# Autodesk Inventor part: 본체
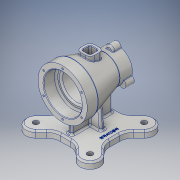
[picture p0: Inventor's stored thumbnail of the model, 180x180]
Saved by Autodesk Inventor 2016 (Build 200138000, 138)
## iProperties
Created: 2018-03
Part Number: 본체
Material: 알루미늄 6061
Document SubType Name: Modeling
Designer: USER
Density: 2.7 g/cm^3
Appearance: 알루미늄 - 평지
Mass: 1010.51 g
Surface Area: 856.88 cm^2
Volume: 374.263 cm^3
Author: USER
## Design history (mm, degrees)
sketch "스케치1"
  geometry: L1 (0, 50)-(0, -50); L2 (36, 50)-(45, 50); L3 (45, 50)-(45, 30.45); L4 (44.868, 29.57)-(27.632, -26.57); L5 (27.5, -27.45)-(27.5, -50); L6 (27.5, -50)-(21, -50); L7 (35, 49)-(35, 30); L8 (32, 27)-(29, 27); L9 (26, 24)-(26, -17); L10 (23, -20)-(23, -20); L11 (20, -23)-(20, -49); L12 (36, 50)-(35, 49); L13 (20, -49)-(21, -50); A1 r 3 centre (32, 30) between (32, 27) and (35, 30); A2 r 3 centre (29, 24) between (29, 27) and (26, 24); A3 r 3 centre (23, -17) between (23, -20) and (26, -17); A4 r 3 centre (42, 30.45) between (44.868, 29.57) and (45, 30.45); A5 r 3 centre (30.5, -27.45) between (27.632, -26.57) and (27.5, -27.45); A6 r 3 centre (23, -23) between (23, -20) and (20, -23); 9 further points
  constraints: 26 end point, 14 point on line, 12 point on circle, 12 tangent, 6 centre point, 5 perpendicular, 4 equal radius, 2 horizontal alignment, 2 vertical, 1 coincident, 1 horizontal, 1 midpoint, 1 parallel
  dimensions: "d0" = 100 distance of L1.start L1.end; "d1" = 70 diameter of L7 L1; "d2" = 52 diameter of L9 L1; "d3" = 40 diameter of L11 L1; "d4" = 90 diameter of L3 L1; "d5" = 55 diameter of L5 L1; "d6" = 77 distance from line of point (27.5, -27) L2; "d7" = 20 distance of L2.end point (45, 30); "d8" = 23 distance of point (35, 50) point (35, 27); "d9" = 47 distance of point (26, 27) point (26, -20); "d10" = 3 radius of A1; "d11" = 1 distance of L2.start point (35, 50); "d12" = 1 distance of L7.start point (35, 50) (= d11); "d13" = 1 distance of L11.end point (20, -50) (= d11); "d14" = 1 distance of L6.end point (20, -50) (= d13); "d15" = 3 radius of A6
revolve "회전1" sketch "스케치1" stored, may be unused: angle "d16" = 90 deg
sketch "스케치2"
  geometry: A1 r 27.5 centre (0, 0) between (0, 27.5) and (-6.943, 26.609) reference; A2 r 7 centre (0, 27.5) between (6.943, 26.609) and (-6.943, 26.609); 1 further point
  constraints: 5 point on circle, 1 centre point, 1 vertical alignment
  dimensions: "d17" = 7 radius of A2
extrude "돌출1" join sketch "스케치2" distance "d18" = 15; taper "d19" = 0 deg
sketch "스케치3"
  geometry: A1 r 7 centre (0, 0) between (6.943, -0.891) and (-6.943, -0.891) reference; 2 further points
  constraints: 1 coincident
hole "구멍1" sketch "스케치3" at (0, 0) diameter "d20" = 3.242; stored, may be unused: countersink angle "d24" = 90 deg, drill point angle "d26" = 118 deg; dims "d21" = 9, "d22" = 4, "d23" = 2, "d25" = 11
fillet "모깎기1" dims "d30" = 1
node "작업 평면1"
sketch "스케치4"
  geometry: L1 (-45, 45)-(45, 45); L2 (45, 45)-(45, -45); L3 (45, -45)-(-45, -45); L4 (-45, -45)-(-45, 45); L5 (-45, 45)-(45, -45); L6 (52.616, 52.616)-(-45, -45); 2 further points
  constraints: 12 end point, 2 parallel, 2 perpendicular, 2 point on line, 1 coincident, 1 horizontal, 1 midpoint, 3 other
  dimensions: "d32" = 90 distance of L1.end L2.end
extrude "돌출2" join sketch "스케치4" distance "d33" = 12; taper "d34" = 0 deg
sketch "스케치6"
  geometry: L1 (45, -45)-(45, 45) reference; L2 (-45, 45)-(45, 45) reference; L3 (-49.497, -49.497)-(49.497, 49.497); L4 (36.77, 62.225)-(19.544, 45); L5 (62.225, 36.77)-(45, 19.544); L6 (45, -45)-(-45, -45) reference; L7 (-45, -45)-(-45, 45) reference; L8 (-49.497, 49.497)-(49.497, -49.497); L9 (62.225, -36.77)-(45, -19.544); L10 (-36.77, -62.225)-(-19.544, -45); L11 (-62.225, 36.77)-(-45, 19.544); L12 (-36.77, 62.225)-(-19.544, 45); L13 (36.77, -62.225)-(19.544, -45); L14 (-62.225, -36.77)-(-45, -19.544); C1 r 5 at (49.497, 49.497); C2 r 5 at (49.497, -49.497); C3 r 5 at (-49.497, -49.497); C4 r 5 at (-49.497, 49.497); A1 r 70 centre (0, 0) between (49.497, 49.497) and (-49.497, -49.497); A2 r 18 centre (49.497, 49.497) between (62.225, 36.77) and (36.77, 62.225); A3 r 18 centre (49.497, -49.497) between (36.77, -62.225) and (62.225, -36.77); A4 r 18 centre (-49.497, -49.497) between (-62.225, -36.77) and (-36.77, -62.225); A5 r 18 centre (-49.497, 49.497) between (-36.77, 62.225) and (-62.225, 36.77); 1 further point
  constraints: 20 end point, 12 point on circle, 9 centre point, 9 coincident, 8 parallel, 8 point on line, 8 tangent, 6 equal radius, 2 midpoint
  dimensions: "d35" = 140 diameter of A1; "d36" = 45 deg angle of L3 L2; "d37" = 10 diameter of C1; "d38" = 18 radius of A2; "d39" = 45 deg angle of L8 L6
extrude "돌출3" join sketch "스케치6" distance "d40" = 12; taper "d41" = 0 deg
fillet "모깎기2" dims "d42" = 25
chamfer "모따기1" distance "d43" = 3; stored, may be unused: second distance "d44" = 2, angle "d45" = 45 deg
sketch "스케치7"
  geometry: L1 (4, -37)-(-4, -37); L2 (-4, -37)-(-4, 37); L3 (-4, 37)-(4, 37); L4 (4, 37)-(4, -37); L5 (4, -37)-(-4, 37); L6 (-4, -37)-(4, 37); 2 further points
  constraints: 12 end point, 4 midpoint, 2 parallel, 1 horizontal, 1 perpendicular
  dimensions: "d46" = 8 distance between parallel lines of L4 L2; "d47" = 37 vertical distance of L1.end point (0, 0)
extrude "돌출4" join sketch "스케치7" stored distance "d48" = 12; taper "d49" = 0 deg
sketch "스케치8"
  geometry: L1 (-4, -70)-(4, -70) reference; L2 (4, -70)-(-4, -70) reference; L3 (44.497, -70)-(54.497, -70) reference; L4 (-54.497, -70)-(-44.497, -70) reference; L5 (-54.497, -70)-(-44.497, -70) reference; L6 (44.497, -70)-(54.497, -70) reference; L7 (50.201, -70)-(42, -70) reference; L8 (60.104, -70)-(50.201, -70) reference; L9 (38.891, -70)-(60.104, -70) reference; L10 (28.988, -70)-(38.891, -70) reference; L11 (9.189, -70)-(28.988, -70) reference; L12 (-9.189, -70)-(9.189, -70) reference; L13 (-28.988, -70)-(-9.189, -70) reference; L14 (-38.891, -70)-(-28.988, -70) reference; L15 (-60.104, -70)-(-38.891, -70) reference; L16 (-50.201, -70)-(-60.104, -70) reference; L17 (-42, -70)-(-50.201, -70) reference; L18 (-50.201, -70)-(-42, -70) reference; L19 (-60.104, -70)-(-50.201, -70) reference; L20 (-38.891, -70)-(-60.104, -70) reference; L21 (-28.988, -70)-(-38.891, -70) reference; L22 (-9.189, -70)-(-28.988, -70) reference; L23 (9.189, -70)-(-9.189, -70) reference; L24 (28.988, -70)-(9.189, -70) reference; L25 (38.891, -70)-(28.988, -70) reference; L26 (60.104, -70)-(38.891, -70) reference; L27 (50.201, -70)-(60.104, -70) reference; L28 (42, -70)-(50.201, -70) reference; L29 (-38.891, -70)-(-28.988, -70) reference; L30 (-24, -70)-(-21.979, -46.903); L31 (28.988, -70)-(38.891, -70) reference; L32 (24, -70)-(22.037, -47.558); 1 further point
  constraints: 4 end point, 2 point on line
  dimensions: "d50" = 24 horizontal distance of L30.start point (0, 0); "d51" = 24 horizontal distance of L32.start point (0, 0); "d52" = 95 deg angle of L30 L21; "d53" = 95 deg angle of L32 L25
  node "투영된 루프1"
feature "리브1" dims "d54" = 1, "d55" = 8, "d56" = 0, "d57" = 0, "d58" = 1, "d59" = 1
feature "리브2" dims "d60" = 1, "d61" = 8, "d62" = 0, "d63" = 0, "d64" = 1, "d65" = 1
fillet "모깎기3" dims "d66" = 3
fillet "모깎기4" dims "d67" = 3
sketch "스케치9"
  geometry: 2 further points
  constraints: 1 horizontal alignment, 1 other
  dimensions: "d68" = 35 distance of point (35, 0) point (0, 0)
feature "엠보싱1" sketch "스케치9" dims "d0" = 100, "d1" = 70, "d2" = 52, "d3" = 40, "d4" = 90, "d5" = 55, "d6" = 77, "d7" = 20, "d8" = 23, "d9" = 47, "d10" = 3, "d11" = 1, "d12" = 1 (= d11), "d13" = 1 (= d11), "d14" = 1 (= d13), "d15" = 3, "d69" = 0.5, "d70" = 0
sketch "스케치10" dims "d71" = 80
  geometry: 3 further points
  constraints: 2 vertical alignment, 1 coincident, 2 other
hole "구멍2" sketch "스케치10" at (0, 40) diameter "d72" = 3.242; stored, may be unused: countersink angle "d76" = 90 deg, drill point angle "d78" = 118 deg; dims "d73" = 9, "d74" = 4, "d75" = 2, "d77" = 11
node "작업 평면2"
sketch "스케치11"
  geometry: L1 (-12.5, 12.5)-(12.5, 12.5); L2 (12.5, 12.5)-(12.5, -12.5); L3 (12.5, -12.5)-(-12.5, -12.5); L4 (-12.5, -12.5)-(-12.5, 12.5); L5 (-12.5, 12.5)-(12.5, -12.5); L6 (12.5, 12.5)-(-12.5, -12.5); 1 further point
  constraints: 12 end point, 2 midpoint, 2 parallel, 2 perpendicular, 1 horizontal
  dimensions: "d83" = 25 distance of L1.end L2.end
extrude "돌출5" join sketch "스케치11" stored distance "d84" = 12; taper "d85" = 0 deg
fillet "모깎기5" dims "d86" = 8
sketch "스케치12"
  geometry: L1 (-4.5, -7.5)-(4.5, -7.5); L2 (7.5, -4.5)-(7.5, 4.5); L3 (4.5, 7.5)-(-4.5, 7.5); L4 (-7.5, 4.5)-(-7.5, -4.5); L5 (-7.5, -7.5)-(7.5, 7.5); L6 (7.5, -7.5)-(-7.5, 7.5); A1 r 3 centre (-4.5, -4.5) between (-7.5, -4.5) and (-4.5, -7.5); A2 r 3 centre (4.5, -4.5) between (4.5, -7.5) and (7.5, -4.5); A3 r 3 centre (4.5, 4.5) between (7.5, 4.5) and (4.5, 7.5); A4 r 3 centre (-4.5, 4.5) between (-4.5, 7.5) and (-7.5, 4.5); 1 further point
  constraints: 12 end point, 8 point on circle, 8 point on line, 8 tangent, 4 centre point, 3 equal radius, 2 midpoint, 2 parallel, 2 perpendicular, 1 horizontal
  dimensions: "d87" = 15 distance of L6.end L5.start; "d88" = 3 radius of A1
extrude "돌출6" cut sketch "스케치12" distance "d89" = 30; taper "d90" = 0 deg
fillet "모깎기6" dims "d91" = 1
chamfer "모따기2" distance "d92" = 1; stored, may be unused: second distance "d93" = 2, angle "d94" = 45 deg
fillet "모깎기7" dims "d95" = 3
fillet "모깎기8" dims "d96" = 1
node "솔리드1"
pattern_circular "원형 패턴1" dims angle "d28" = 360 deg
pattern_circular "원형 패턴2" dims angle "d80" = 360 deg
other parameters: "d31" = -82, "d82" = 45
